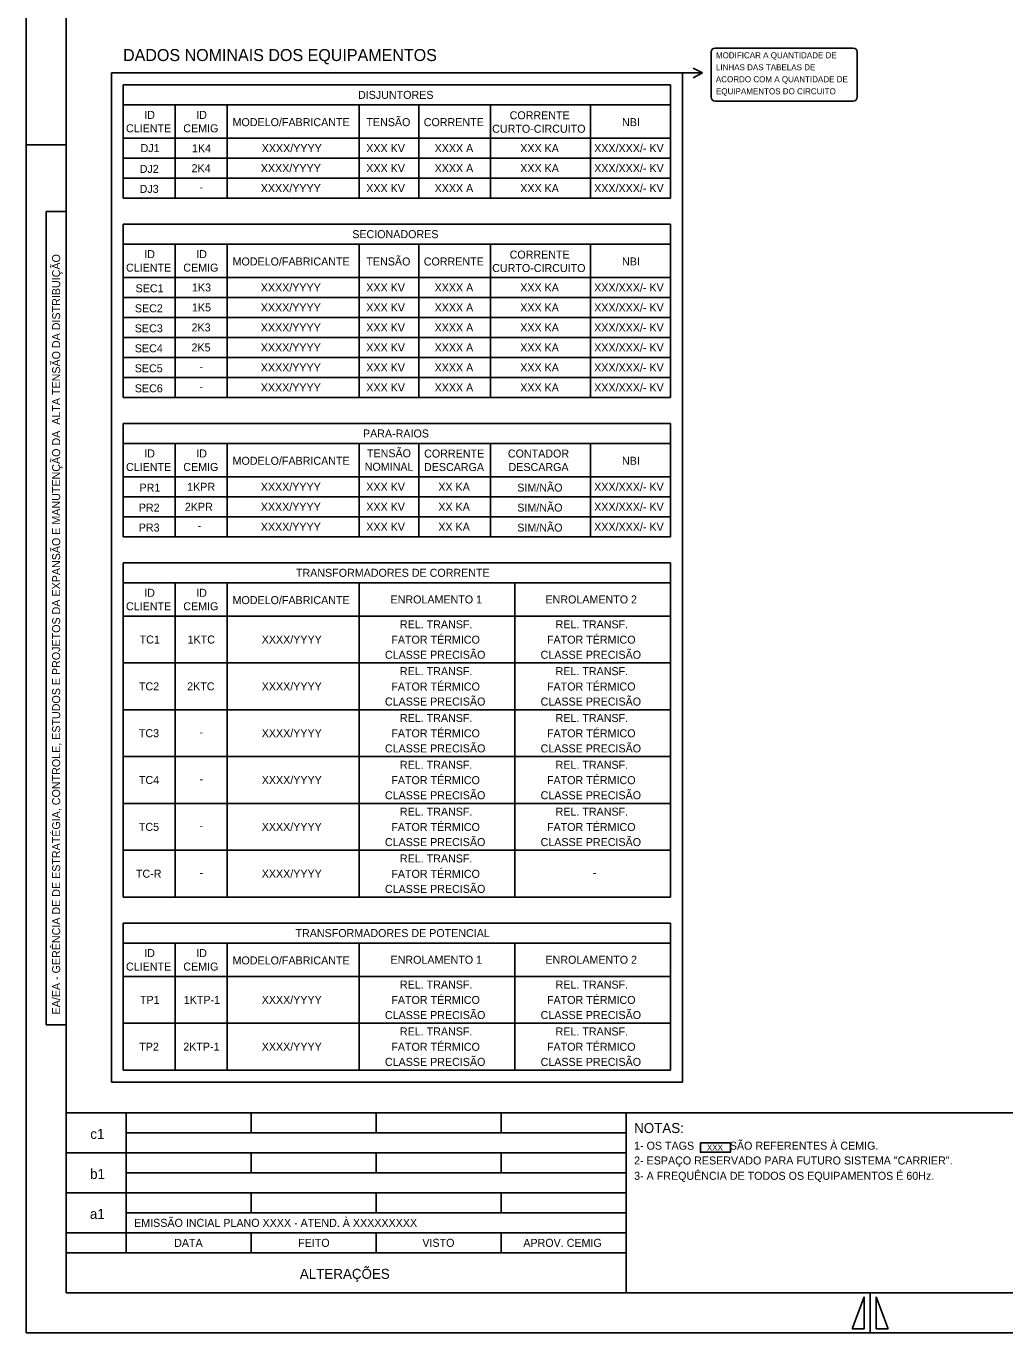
# Model space of a CAD drawing. Extents: x 501 to 1404, y 358 to 952.
# Drawn here: x 562.6 to 807.3, y 358 to 684.6 of the extents above; entities that cross this region are included whole.
import ezdxf

# ---------------------------------------------------------------- set-up
doc = ezdxf.new("R2010")
doc.units = 0
doc.layers.add('New Level (0)', color=7, linetype='Continuous')

# ---------------------------------------------------------------- blocks, each defined once
blk = doc.blocks.new('POINT_DISPLAY')
blk.add_line((0, 0), (0, 0))

msp = doc.modelspace()

# ---------------------------------------------------------------- linework, layer by layer
at = {"layer": 'New Level (0)'}
for p, q in [((562.58, 951.96), (562.58, 357.96)), ((562.58, 951.96), (562.58, 357.96)), ((572.58, 941.96), (572.58, 367.96)), ((572.58, 941.96), (572.58, 367.96)), ((733.84, 666.91), (733.84, 678.16)), ((734.84, 679.16), (742.19, 679.16)), ((742.19, 679.16), (769.38, 679.16)), ((770.38, 678.16), (770.38, 666.91)), ((731.68, 672.95), (729.38, 674.16)), ((583.96, 672.95), (583.96, 420.65)), ((583.96, 672.95), (726.65, 672.95)), ((586.81, 669.95), (586.81, 641.63)), ((586.81, 669.95), (723.65, 669.95)), ((723.65, 669.95), (723.65, 641.63)), ((726.65, 672.95), (726.65, 420.65)), ((726.65, 672.95), (731.68, 672.95)), ((731.68, 672.95), (729.38, 671.75)), ((723.65, 664.95), (586.81, 664.95)), ((599.81, 664.95), (599.81, 641.63)), ((612.81, 641.63), (612.81, 664.95)), ((645.81, 664.95), (645.81, 641.63)), ((660.72, 664.95), (660.72, 641.63)), ((678.66, 664.95), (678.66, 641.63)), ((703.66, 664.95), (703.66, 641.63)), ((769.38, 665.91), (734.84, 665.91)), ((562.58, 654.96), (572.58, 654.96)), ((586.81, 656.63), (723.65, 656.63)), ((586.81, 651.63), (723.65, 651.63)), ((586.81, 646.63), (723.65, 646.63)), ((586.81, 641.63), (723.65, 641.63)), ((567.58, 638.29), (572.58, 638.29)), ((567.58, 434.97), (567.58, 638.29)), ((586.81, 635.13), (586.81, 591.8)), ((586.81, 635.13), (723.65, 635.13)), ((723.65, 635.13), (723.65, 591.8)), ((723.65, 630.13), (586.81, 630.13)), ((599.81, 630.13), (599.81, 591.8)), ((612.81, 591.8), (612.81, 630.13)), ((645.81, 630.13), (645.81, 591.8)), ((660.72, 630.13), (660.72, 591.8)), ((678.66, 630.13), (678.66, 591.8)), ((703.66, 630.13), (703.66, 591.8)), ((586.81, 621.8), (723.65, 621.8)), ((586.81, 616.8), (723.65, 616.8)), ((586.81, 611.8), (723.65, 611.8)), ((586.81, 606.8), (723.65, 606.8)), ((586.81, 601.8), (723.65, 601.8)), ((586.81, 596.8), (723.65, 596.8)), ((586.81, 591.8), (723.65, 591.8)), ((586.81, 585.3), (586.81, 556.97)), ((586.81, 585.3), (723.65, 585.3)), ((723.65, 585.3), (723.65, 556.97)), ((723.65, 580.3), (586.81, 580.3)), ((599.81, 580.3), (599.81, 556.97)), ((612.81, 556.97), (612.81, 580.3)), ((645.81, 580.3), (645.81, 556.97)), ((660.72, 580.3), (660.72, 556.97)), ((678.66, 580.3), (678.66, 556.97)), ((703.66, 580.3), (703.66, 556.97)), ((586.81, 571.97), (723.65, 571.97)), ((629.06, 571.97), (723.65, 571.97)), ((586.81, 566.97), (723.65, 566.97)), ((586.81, 561.97), (723.65, 561.97)), ((586.81, 556.97), (723.65, 556.97)), ((586.81, 550.47), (586.81, 466.9)), ((586.81, 550.47), (723.65, 550.47)), ((723.65, 550.47), (723.65, 466.9)), ((723.65, 545.47), (586.81, 545.47)), ((599.81, 545.47), (599.81, 466.9)), ((612.81, 466.9), (612.81, 545.47)), ((645.81, 545.47), (645.81, 466.9)), ((684.73, 545.47), (684.73, 466.9)), ((586.81, 537.14), (723.65, 537.14)), ((586.81, 525.44), (723.65, 525.44)), ((586.81, 513.73), (723.65, 513.73)), ((586.81, 502.02), (723.65, 502.02)), ((586.81, 490.31), (723.65, 490.31)), ((586.81, 478.6), (723.65, 478.6)), ((586.81, 466.9), (723.65, 466.9)), ((586.81, 466.9), (586.81, 466.9)), ((586.81, 460.4), (586.81, 423.65)), ((586.81, 460.4), (723.65, 460.4)), ((723.65, 460.4), (723.65, 423.65)), ((723.65, 455.4), (586.81, 455.4)), ((599.81, 455.4), (599.81, 423.65)), ((612.81, 423.65), (612.81, 455.4)), ((645.81, 455.4), (645.81, 423.65)), ((684.73, 455.4), (684.73, 423.65)), ((586.81, 447.07), (723.65, 447.07)), ((572.58, 434.97), (567.58, 434.97)), ((586.81, 435.36), (723.65, 435.36)), ((586.81, 423.65), (723.65, 423.65)), ((726.65, 420.65), (583.96, 420.65)), ((572.58, 412.96), (1393.58, 412.96)), ((587.58, 377.96), (587.58, 412.96)), ((618.83, 407.96), (618.83, 412.96)), ((650.08, 407.96), (650.08, 412.96)), ((681.33, 407.96), (681.33, 412.96)), ((712.58, 412.96), (712.58, 367.96)), ((587.58, 407.96), (712.58, 407.96)), ((572.58, 402.96), (712.58, 402.96)), ((618.83, 397.96), (618.83, 402.96)), ((650.08, 397.96), (650.08, 402.96)), ((681.33, 397.96), (681.33, 402.96)), ((587.58, 397.96), (712.58, 397.96)), ((572.58, 392.96), (712.58, 392.96)), ((618.83, 387.96), (618.83, 392.96)), ((650.08, 387.96), (650.08, 392.96)), ((681.33, 387.96), (681.33, 392.96)), ((587.58, 387.96), (712.58, 387.96)), ((572.58, 382.96), (712.58, 382.96)), ((618.83, 377.96), (618.83, 382.96)), ((650.08, 377.96), (650.08, 382.96)), ((681.33, 377.96), (681.33, 382.96)), ((572.58, 377.96), (712.58, 377.96)), ((572.58, 367.96), (1393.58, 367.96)), ((572.58, 367.96), (1393.58, 367.96)), ((769.08, 358.96), (772.08, 366.96)), ((772.08, 366.96), (772.08, 358.96)), ((773.58, 367.96), (773.58, 357.96)), ((775.08, 366.96), (775.08, 358.96)), ((778.08, 358.96), (775.08, 366.96)), ((562.58, 357.96), (1403.58, 357.96)), ((562.58, 357.96), (1403.58, 357.96)), ((772.08, 358.96), (769.08, 358.96)), ((775.08, 358.96), (778.08, 358.96))]:
    msp.add_line(p, q, dxfattribs=at)
msp.add_lwpolyline([(731.16, 405.44), (738.67, 405.44), (738.67, 403.1), (731.16, 403.1)], close=True, dxfattribs=at)
for centre, start, end in [((734.84, 678.16), 90, 180), ((769.38, 678.16), 0, 90), ((734.84, 666.91), 180, 270), ((769.38, 666.91), 270, 0)]:
    msp.add_arc(centre, 1, start, end, dxfattribs=at)

# ---------------------------------------------------------------- block references
for p in [(655.23, 656.63), (655.23, 537.14), (655.23, 447.07)]:
    msp.add_blockref('POINT_DISPLAY', p, dxfattribs=at)

# ---------------------------------------------------------------- texts
for s, height, p in [('DADOS NOMINAIS DOS EQUIPAMENTOS', 3, (586.81, 675.91)), ('MODIFICAR A QUANTIDADE DE ', 1.5, (735.03, 676.61)), ('LINHAS DAS TABELAS DE ', 1.5, (735.03, 673.61)), ('ACORDO COM A QUANTIDADE DE ', 1.5, (735.03, 670.61)), ('DISJUNTORES', 2, (645.55, 666.45)), ('EQUIPAMENTOS DO CIRCUITO', 1.5, (735.03, 667.61)), ('ID', 2, (592.1, 661.45)), ('ID', 2, (605.1, 661.45)), ('CORRENTE', 2, (683.46, 661.35)), ('CLIENTE', 2, (587.54, 658.09)), ('CEMIG', 2, (601.87, 658.09)), ('MODELO/FABRICANTE', 2, (614.19, 659.63)), ('TENSÃO', 2, (647.65, 659.63)), ('CORRENTE', 2, (661.99, 659.63)), ('CURTO-CIRCUITO', 2, (679.1, 657.98)), ('NBI', 2, (711.56, 659.63)), ('DJ1', 2, (591.19, 653.14)), ('1K4', 2, (604.05, 653.12)), ('XXXX/YYYY', 2, (621.48, 653.13)), ('XXX KV', 2, (647.62, 653.13)), ('XXXX A', 2, (664.7, 653.13)), ('XXX KA', 2, (686.11, 653.13)), ('XXX/XXX/- KV', 2, (704.59, 653.13)), ('2K4', 2, (603.94, 648.12)), ('XXXX/YYYY', 2, (621.24, 648.13)), ('XXX KV', 2, (647.62, 648.13)), ('XXXX A', 2, (664.7, 648.13)), ('XXX KA', 2, (686.11, 648.13)), ('XXX/XXX/- KV', 2, (704.59, 648.13)), ('DJ2', 2, (590.97, 647.95)), ('DJ3', 2, (590.96, 642.95)), ('-', 2, (605.94, 643.4)), ('XXXX/YYYY', 2, (621.24, 643.13)), ('XXX KV', 2, (647.62, 643.13)), ('XXXX A', 2, (664.7, 643.13)), ('XXX KA', 2, (686.11, 643.13)), ('XXX/XXX/- KV', 2, (704.59, 643.13)), ('SECIONADORES', 2, (644.11, 631.63)), ('ID', 2, (592.1, 626.63)), ('ID', 2, (605.1, 626.63)), ('TENSÃO', 2, (647.65, 624.8)), ('CORRENTE', 2, (683.46, 626.52)), ('CLIENTE', 2, (587.54, 623.26)), ('CEMIG', 2, (601.87, 623.26)), ('MODELO/FABRICANTE', 2, (614.19, 624.8)), ('CORRENTE', 2, (661.99, 624.8)), ('CURTO-CIRCUITO', 2, (679.1, 623.16)), ('NBI', 2, (711.56, 624.8)), ('SEC1', 2, (589.94, 618.1)), ('1K3', 2, (604.04, 618.31)), ('XXXX/YYYY', 2, (621.24, 618.3)), ('XXX KV', 2, (647.62, 618.3)), ('XXXX A', 2, (664.7, 618.3)), ('XXX KA', 2, (686.11, 618.3)), ('XXX/XXX/- KV', 2, (704.59, 618.3)), ('SEC2', 2, (589.76, 613.1)), ('1K5', 2, (604.04, 613.31)), ('XXXX/YYYY', 2, (621.24, 613.3)), ('XXX KV', 2, (647.62, 613.3)), ('XXXX A', 2, (664.7, 613.3)), ('XXX KA', 2, (686.11, 613.3)), ('XXX/XXX/- KV', 2, (704.59, 613.3)), ('SEC3', 2, (589.75, 608.1)), ('2K3', 2, (603.93, 608.31)), ('XXXX/YYYY', 2, (621.24, 608.3)), ('XXX KV', 2, (647.62, 608.3)), ('XXXX A', 2, (664.7, 608.3)), ('XXX KA', 2, (686.11, 608.3)), ('XXX/XXX/- KV', 2, (704.59, 608.3)), ('SEC4', 2, (589.75, 603.1)), ('2K5', 2, (603.92, 603.31)), ('XXXX/YYYY', 2, (621.24, 603.3)), ('XXX KV', 2, (647.62, 603.3)), ('XXXX A', 2, (664.7, 603.3)), ('XXX KA', 2, (686.11, 603.3)), ('XXX/XXX/- KV', 2, (704.59, 603.3)), ('SEC5', 2, (589.74, 598.1)), ('-', 2, (605.94, 598.57)), ('XXXX/YYYY', 2, (621.24, 598.3)), ('XXX KV', 2, (647.62, 598.3)), ('XXXX A', 2, (664.7, 598.3)), ('XXX KA', 2, (686.11, 598.3)), ('XXX/XXX/- KV', 2, (704.59, 598.3)), ('SEC6', 2, (589.75, 593.1)), ('XXXX/YYYY', 2, (621.24, 593.3)), ('XXX KV', 2, (647.62, 593.3)), ('XXXX A', 2, (664.7, 593.3)), ('XXX KA', 2, (686.11, 593.3)), ('XXX/XXX/- KV', 2, (704.59, 593.3)), ('-', 2, (605.94, 593.57)), ('PARA-RAIOS', 2, (646.79, 581.8)), ('ID', 2, (592.1, 576.8)), ('ID', 2, (605.1, 576.8)), ('TENSÃO ', 2, (647.79, 576.85)), ('CORRENTE', 2, (662.09, 576.78)), ('CONTADOR', 2, (683.02, 576.78)), ('CLIENTE', 2, (587.54, 573.43)), ('CEMIG', 2, (601.87, 573.43)), ('MODELO/FABRICANTE', 2, (614.19, 574.97)), ('NOMINAL', 2, (647.23, 573.48)), ('DESCARGA', 2, (662.05, 573.41)), ('DESCARGA', 2, (683.19, 573.41)), ('NBI', 2, (711.56, 574.97)), ('PR1', 2, (590.92, 568.27)), ('1KPR', 2, (602.83, 568.47)), ('XXXX/YYYY', 2, (621.24, 568.47)), ('XXX KV', 2, (647.62, 568.47)), ('XX KA', 2, (665.63, 568.47)), ('SIM/NÃO', 2, (685.38, 568.27)), ('XXX/XXX/- KV', 2, (704.59, 568.47)), ('PR2', 2, (590.74, 563.27)), ('2KPR', 2, (602.26, 563.47)), ('XXXX/YYYY', 2, (621.24, 563.47)), ('XXX KV', 2, (647.62, 563.47)), ('XX KA', 2, (665.63, 563.47)), ('SIM/NÃO', 2, (685.38, 563.27)), ('XXX/XXX/- KV', 2, (704.59, 563.47)), ('PR3', 2, (590.73, 558.29)), ('-', 2, (605.47, 558.75)), ('XXXX/YYYY', 2, (621.24, 558.47)), ('XXX KV', 2, (647.62, 558.47)), ('XX KA', 2, (665.63, 558.47)), ('SIM/NÃO', 2, (685.38, 558.27)), ('XXX/XXX/- KV', 2, (704.59, 558.47)), ('TRANSFORMADORES DE CORRENTE', 2, (630.03, 546.97)), ('ID', 2, (592.1, 541.97)), ('ID', 2, (605.1, 541.97)), ('ENROLAMENTO 1', 2, (653.68, 540.31)), ('ENROLAMENTO 2', 2, (692.42, 540.31)), ('CLIENTE', 2, (587.54, 538.6)), ('CEMIG', 2, (601.87, 538.6)), ('MODELO/FABRICANTE', 2, (614.19, 540.14)), ('REL. TRANSF.', 2, (656.03, 534.09)), ('REL. TRANSF.', 2, (694.95, 534.09)), ('FATOR TÉRMICO', 2, (653.88, 530.25)), ('FATOR TÉRMICO', 2, (692.8, 530.25)), ('TC1', 2, (590.96, 530.29)), ('1KTC', 2, (602.95, 530.29)), ('XXXX/YYYY', 2, (621.48, 530.29)), ('CLASSE PRECISÃO', 2, (652.28, 526.48)), ('CLASSE PRECISÃO', 2, (691.2, 526.48)), ('REL. TRANSF.', 2, (656.03, 522.38)), ('REL. TRANSF.', 2, (694.95, 522.38)), ('TC2', 2, (590.78, 518.58)), ('2KTC', 2, (602.84, 518.58)), ('XXXX/YYYY', 2, (621.48, 518.58)), ('FATOR TÉRMICO', 2, (653.88, 518.54)), ('FATOR TÉRMICO', 2, (692.8, 518.54)), ('CLASSE PRECISÃO', 2, (652.28, 514.78)), ('CLASSE PRECISÃO', 2, (691.2, 514.78)), ('REL. TRANSF.', 2, (656.03, 510.68)), ('REL. TRANSF.', 2, (694.95, 510.68)), ('TC3', 2, (590.77, 506.87)), ('-', 2, (605.94, 507.15)), ('XXXX/YYYY', 2, (621.48, 506.87)), ('FATOR TÉRMICO', 2, (653.88, 506.84)), ('FATOR TÉRMICO', 2, (692.8, 506.84)), ('CLASSE PRECISÃO', 2, (652.28, 503.07)), ('CLASSE PRECISÃO', 2, (691.2, 503.07)), ('REL. TRANSF.', 2, (656.03, 498.97)), ('REL. TRANSF.', 2, (694.95, 498.97)), ('TC4', 2, (590.78, 495.17)), ('XXXX/YYYY', 2, (621.48, 495.17)), ('FATOR TÉRMICO', 2, (653.88, 495.13)), ('FATOR TÉRMICO', 2, (692.8, 495.13)), ('-', 2, (605.94, 495.44)), ('CLASSE PRECISÃO', 2, (652.28, 491.36)), ('CLASSE PRECISÃO', 2, (691.2, 491.36)), ('REL. TRANSF.', 2, (656.03, 487.26)), ('REL. TRANSF.', 2, (694.95, 487.26)), ('TC5', 2, (590.76, 483.46)), ('-', 2, (605.94, 483.73)), ('XXXX/YYYY', 2, (621.48, 483.46)), ('FATOR TÉRMICO', 2, (653.88, 483.42)), ('FATOR TÉRMICO', 2, (692.8, 483.42)), ('CLASSE PRECISÃO', 2, (652.28, 479.65)), ('CLASSE PRECISÃO', 2, (691.2, 479.65)), ('REL. TRANSF.', 2, (656.03, 475.55)), ('TC-R', 2, (590.03, 471.75)), ('XXXX/YYYY', 2, (621.48, 471.75)), ('FATOR TÉRMICO', 2, (653.88, 471.71)), ('-', 2, (605.94, 472.03)), ('CLASSE PRECISÃO', 2, (652.28, 467.95)), ('-', 2, (704.25, 472.03)), ('TRANSFORMADORES DE POTENCIAL', 2, (629.92, 456.9)), ('ID', 2, (592.1, 451.9)), ('ID', 2, (605.1, 451.9)), ('MODELO/FABRICANTE', 2, (614.19, 450.07)), ('ENROLAMENTO 1', 2, (653.68, 450.23)), ('ENROLAMENTO 2', 2, (692.42, 450.23)), ('CLIENTE', 2, (587.54, 448.53)), ('CEMIG', 2, (601.87, 448.53)), ('REL. TRANSF.', 2, (656.03, 444.02)), ('REL. TRANSF.', 2, (694.95, 444.02)), ('TP1', 2, (591.04, 440.21)), ('1KTP-1', 2, (601.99, 440.21)), ('XXXX/YYYY', 2, (621.48, 440.21)), ('FATOR TÉRMICO', 2, (653.88, 440.18)), ('FATOR TÉRMICO', 2, (692.8, 440.18)), ('CLASSE PRECISÃO', 2, (652.28, 436.41)), ('CLASSE PRECISÃO', 2, (691.2, 436.41)), ('REL. TRANSF.', 2, (656.03, 432.31)), ('REL. TRANSF.', 2, (694.95, 432.31)), ('TP2', 2, (590.86, 428.5)), ('2KTP-1', 2, (601.87, 428.5)), ('XXXX/YYYY', 2, (621.48, 428.51)), ('FATOR TÉRMICO', 2, (653.88, 428.47)), ('FATOR TÉRMICO', 2, (692.8, 428.47)), ('CLASSE PRECISÃO', 2, (652.28, 424.7)), ('CLASSE PRECISÃO', 2, (691.2, 424.7)), ('XXX', 1.5, (732.77, 403.54))]:
    msp.add_text(s, height=height).set_placement(p)
msp.add_text('EA/EA - GERÊNCIA DE DE ESTRATÉGIA, CONTROLE, ESTUDOS E PROJETOS DA EXPANSÃO E MANUTENÇÃO DA  ALTA TENSÃO DA DISTRIBUIÇÃO', height=2, rotation=90, dxfattribs=at).set_placement((571.08, 437.56))
for s, height, p in [('c1', 2.5, (578.62, 406.44)), ('NOTAS:', 2.5, (714.58, 407.91)), ('1- OS TAGS            SÃO REFERENTES À CEMIG.', 2, (714.58, 403.75)), ('2- ESPAÇO RESERVADO PARA FUTURO SISTEMA "CARRIER".', 2, (714.58, 400.05)), ('b1', 2.5, (578.57, 396.44)), ('3- A FREQUÊNCIA DE TODOS OS EQUIPAMENTOS É 60Hz.', 2, (714.58, 396.22)), ('a1', 2.5, (578.52, 386.44)), ('EMISSÃO INCIAL PLANO XXXX - ATEND. À XXXXXXXXX', 2, (589.58, 384.46)), ('DATA', 2, (599.58, 379.46)), ('FEITO', 2, (630.58, 379.46)), ('VISTO', 2, (661.64, 379.46)), ('APROV. CEMIG', 2, (686.88, 379.46)), ('ALTERAÇÕES', 2.5, (631.01, 371.46))]:
    msp.add_text(s, height=height, dxfattribs=at).set_placement(p)

doc.saveas('drawing.dxf')
